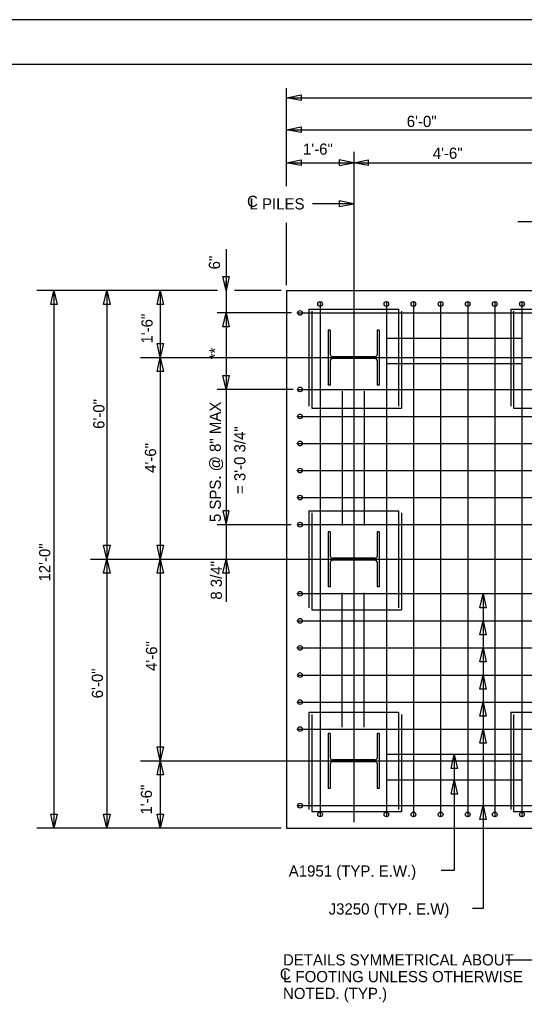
# Model space of a CAD drawing. Extents: x 1970675.2 to 1970711.3, y 796145.2 to 796167.2.
# Drawn here: x 1970688.24 to 1970693.86, y 796156.28 to 796167.25 of the extents above; entities that cross this region are included whole.
import ezdxf

# ---------------------------------------------------------------- set-up
doc = ezdxf.new("R2010")
doc.units = 0
for name, color, linetype in [('BR_AUTO DIMENSION', 7, 'Continuous'), ('BR_BORDER LINES', 7, 'Continuous'), ('BR_CENTER LINES', 7, 'Continuous'), ('BR_CONCRETE', 7, 'Continuous'), ('BR_REBAR', 7, 'Continuous'), ('BR_STRUCTURAL STEEL', 7, 'Continuous'), ('BR_TEXT', 7, 'Continuous'), ('Level 31', 7, 'Continuous')]:
    doc.layers.add(name, color=color, linetype=linetype)

msp = doc.modelspace()

# ---------------------------------------------------------------- linework, layer by layer
at = {"layer": 'BR_AUTO DIMENSION'}
for p, q in [((1970691.212, 796165.389), (1970691.212, 796166.48)), ((1970691.212, 796166.375), (1970697.212, 796166.375)), ((1970691.212, 796166.018), (1970694.212, 796166.018)), ((1970691.212, 796165.65), (1970691.962, 796165.65)), ((1970691.962, 796165.65), (1970694.212, 796165.65)), ((1970691.962, 796165.192), (1970691.501, 796165.192)), ((1970691.212, 796164.284), (1970691.212, 796164.977)), ((1970694.212, 796164.991), (1970693.791, 796164.991)), ((1970690.538, 796164.684), (1970690.538, 796160.748)), ((1970690.538, 796164.224), (1970690.538, 796164.327)), ((1970690.443, 796164.224), (1970688.427, 796164.224)), ((1970688.619, 796164.224), (1970688.619, 796158.224)), ((1970689.208, 796164.224), (1970689.208, 796161.224)), ((1970689.805, 796164.224), (1970689.805, 796163.474)), ((1970691.152, 796164.224), (1970690.631, 796164.224)), ((1970691.268, 796163.974), (1970690.439, 796163.974)), ((1970689.805, 796163.474), (1970689.805, 796161.224)), ((1970691.285, 796163.12), (1970690.439, 796163.12)), ((1970691.265, 796161.61), (1970690.439, 796161.61)), ((1970689.208, 796161.224), (1970689.208, 796158.224)), ((1970689.805, 796161.224), (1970689.805, 796158.224)), ((1970693.404, 796160.839), (1970693.404, 796157.326)), ((1970693.083, 796159.044), (1970693.083, 796157.751)), ((1970689.805, 796158.849), (1970689.805, 796158.75)), ((1970691.152, 796158.224), (1970688.427, 796158.224)), ((1970689.805, 796158.224), (1970689.805, 796158.314)), ((1970693.083, 796157.751), (1970692.938, 796157.751)), ((1970693.404, 796157.326), (1970693.287, 796157.326)), ((1970694.212, 796156.751), (1970693.66, 796156.751))]:
    msp.add_line(p, q, dxfattribs=at)
for points in [[(1970691.374, 796166.344), (1970691.212, 796166.375), (1970691.374, 796166.407)], [(1970691.374, 796165.987), (1970691.212, 796166.018), (1970691.374, 796166.049)], [(1970691.374, 796165.619), (1970691.212, 796165.65), (1970691.374, 796165.681)], [(1970691.799, 796165.619), (1970691.962, 796165.65), (1970691.799, 796165.681)], [(1970692.124, 796165.619), (1970691.962, 796165.65), (1970692.124, 796165.681)], [(1970691.799, 796165.161), (1970691.962, 796165.192), (1970691.799, 796165.223)], [(1970690.574, 796164.38), (1970690.538, 796164.224), (1970690.502, 796164.38)], [(1970688.583, 796164.068), (1970688.619, 796164.224), (1970688.655, 796164.068)], [(1970689.172, 796164.068), (1970689.208, 796164.224), (1970689.244, 796164.068)], [(1970689.769, 796164.068), (1970689.805, 796164.224), (1970689.841, 796164.068)], [(1970690.502, 796163.818), (1970690.538, 796163.974), (1970690.574, 796163.818)], [(1970689.841, 796163.632), (1970689.805, 796163.476), (1970689.769, 796163.632)], [(1970689.769, 796163.318), (1970689.805, 796163.474), (1970689.841, 796163.318)], [(1970690.574, 796163.276), (1970690.538, 796163.12), (1970690.502, 796163.276)], [(1970690.502, 796161.766), (1970690.538, 796161.61), (1970690.574, 796161.766)], [(1970689.244, 796161.38), (1970689.208, 796161.224), (1970689.172, 796161.38)], [(1970689.841, 796161.38), (1970689.805, 796161.224), (1970689.769, 796161.38)], [(1970689.172, 796161.068), (1970689.208, 796161.224), (1970689.244, 796161.068)], [(1970689.769, 796161.068), (1970689.805, 796161.224), (1970689.841, 796161.068)], [(1970690.502, 796161.068), (1970690.538, 796161.224), (1970690.574, 796161.068)], [(1970693.368, 796160.683), (1970693.404, 796160.839), (1970693.44, 796160.683)], [(1970693.368, 796160.381), (1970693.404, 796160.537), (1970693.44, 796160.381)], [(1970693.368, 796160.079), (1970693.404, 796160.235), (1970693.44, 796160.079)], [(1970693.368, 796159.776), (1970693.404, 796159.932), (1970693.44, 796159.776)], [(1970693.368, 796159.474), (1970693.404, 796159.63), (1970693.44, 796159.474)], [(1970693.368, 796159.172), (1970693.404, 796159.328), (1970693.44, 796159.172)], [(1970689.841, 796159.13), (1970689.805, 796158.974), (1970689.769, 796159.13)], [(1970689.769, 796158.818), (1970689.805, 796158.974), (1970689.841, 796158.818)], [(1970693.047, 796158.888), (1970693.083, 796159.044), (1970693.119, 796158.888)], [(1970693.047, 796158.603), (1970693.083, 796158.759), (1970693.119, 796158.603)], [(1970693.368, 796158.318), (1970693.404, 796158.474), (1970693.44, 796158.318)], [(1970688.655, 796158.38), (1970688.619, 796158.224), (1970688.583, 796158.38)], [(1970689.244, 796158.38), (1970689.208, 796158.224), (1970689.172, 796158.38)], [(1970689.841, 796158.38), (1970689.805, 796158.224), (1970689.769, 796158.38)]]:
    msp.add_lwpolyline(points, close=True, dxfattribs=at)
at = {"layer": 'BR_BORDER LINES'}
msp.add_line((1970710.736, 796166.746), (1970677.07, 796166.746), dxfattribs=at)
at = {"layer": 'BR_CENTER LINES'}
for p, q in [((1970691.962, 796165.772), (1970691.962, 796158.288)), ((1970689.584, 796163.474), (1970698.529, 796163.474)), ((1970689.028, 796161.224), (1970699.302, 796161.224)), ((1970689.584, 796158.974), (1970698.439, 796158.974))]:
    msp.add_line(p, q, dxfattribs=at)
at = {"layer": 'BR_CONCRETE'}
for p, q in [((1970691.212, 796164.224), (1970697.212, 796164.224)), ((1970691.212, 796164.224), (1970691.212, 796158.224)), ((1970691.212, 796158.224), (1970697.212, 796158.224))]:
    msp.add_line(p, q, dxfattribs=at)
at = {"layer": 'BR_REBAR'}
for p, q in [((1970691.587, 796164.099), (1970691.587, 796158.349)), ((1970692.326, 796164.099), (1970692.326, 796158.349)), ((1970692.628, 796164.099), (1970692.628, 796158.349)), ((1970692.931, 796164.099), (1970692.931, 796158.349)), ((1970693.233, 796164.099), (1970693.233, 796158.349)), ((1970693.535, 796164.099), (1970693.535, 796158.349)), ((1970693.837, 796164.099), (1970693.837, 796158.349)), ((1970691.337, 796163.974), (1970697.087, 796163.974)), ((1970691.462, 796164.016), (1970692.462, 796164.016)), ((1970691.462, 796164.016), (1970691.462, 796162.932)), ((1970691.494, 796163.993), (1970691.494, 796162.91)), ((1970692.462, 796164.016), (1970692.462, 796162.932)), ((1970692.494, 796163.993), (1970692.494, 796162.91)), ((1970693.712, 796164.016), (1970694.712, 796164.016)), ((1970693.712, 796164.016), (1970693.712, 796162.932)), ((1970693.744, 796163.993), (1970693.744, 796162.91)), ((1970693.837, 796163.689), (1970692.337, 796163.689)), ((1970693.837, 796163.405), (1970692.337, 796163.405)), ((1970691.337, 796163.12), (1970697.087, 796163.12)), ((1970691.833, 796163.099), (1970691.833, 796161.599)), ((1970692.08, 796163.099), (1970692.08, 796161.599)), ((1970691.337, 796162.818), (1970697.087, 796162.818)), ((1970691.494, 796162.91), (1970692.494, 796162.91)), ((1970693.744, 796162.91), (1970694.744, 796162.91)), ((1970691.337, 796162.516), (1970697.087, 796162.516)), ((1970691.337, 796162.214), (1970697.087, 796162.214)), ((1970691.337, 796161.912), (1970697.087, 796161.912)), ((1970691.462, 796161.766), (1970692.462, 796161.766)), ((1970691.462, 796161.766), (1970691.462, 796160.682)), ((1970691.494, 796161.743), (1970691.494, 796160.66)), ((1970692.462, 796161.766), (1970692.462, 796160.682)), ((1970692.494, 796161.743), (1970692.494, 796160.66)), ((1970697.087, 796161.61), (1970691.337, 796161.61)), ((1970692.42, 796161.224), (1970696.003, 796161.224)), ((1970697.087, 796160.839), (1970691.337, 796160.839)), ((1970691.833, 796159.349), (1970691.833, 796160.849)), ((1970692.08, 796159.349), (1970692.08, 796160.849)), ((1970691.494, 796160.66), (1970692.494, 796160.66)), ((1970691.337, 796160.537), (1970697.087, 796160.537)), ((1970691.337, 796160.235), (1970697.087, 796160.235)), ((1970691.337, 796159.932), (1970697.087, 796159.932)), ((1970691.337, 796159.63), (1970697.087, 796159.63)), ((1970691.462, 796159.516), (1970692.462, 796159.516)), ((1970691.462, 796159.516), (1970691.462, 796158.432)), ((1970691.494, 796159.493), (1970691.494, 796158.41)), ((1970692.462, 796159.516), (1970692.462, 796158.432)), ((1970692.494, 796159.493), (1970692.494, 796158.41)), ((1970693.712, 796159.516), (1970694.712, 796159.516)), ((1970693.712, 796159.516), (1970693.712, 796158.432)), ((1970693.744, 796159.493), (1970693.744, 796158.41)), ((1970691.337, 796159.328), (1970697.087, 796159.328)), ((1970693.837, 796159.044), (1970692.337, 796159.044)), ((1970693.837, 796158.759), (1970692.337, 796158.759)), ((1970691.337, 796158.474), (1970697.087, 796158.474)), ((1970691.494, 796158.41), (1970692.494, 796158.41)), ((1970693.744, 796158.41), (1970694.744, 796158.41))]:
    msp.add_line(p, q, dxfattribs=at)
for centre in [(1970691.587, 796164.073), (1970692.326, 796164.073), (1970692.628, 796164.073), (1970692.931, 796164.073), (1970693.233, 796164.073), (1970693.535, 796164.073), (1970693.837, 796164.073), (1970691.363, 796163.974), (1970691.363, 796163.12), (1970691.363, 796162.818), (1970691.363, 796162.516), (1970691.363, 796162.214), (1970691.363, 796161.912), (1970691.363, 796161.61), (1970691.363, 796160.839), (1970691.363, 796160.537), (1970691.363, 796160.235), (1970691.363, 796159.932), (1970691.363, 796159.63), (1970691.363, 796159.328), (1970691.363, 796158.474), (1970691.587, 796158.376), (1970692.326, 796158.376), (1970692.628, 796158.376), (1970692.931, 796158.376), (1970693.233, 796158.376), (1970693.535, 796158.376), (1970693.837, 796158.376)]:
    msp.add_circle(centre, 0.0265, dxfattribs=at)
at = {"layer": 'BR_STRUCTURAL STEEL'}
for p, q in [((1970691.678, 796163.781), (1970691.678, 796163.167)), ((1970691.699, 796163.781), (1970691.678, 796163.781)), ((1970691.699, 796163.781), (1970691.699, 796163.513)), ((1970692.225, 796163.781), (1970692.225, 796163.513)), ((1970692.246, 796163.781), (1970692.225, 796163.781)), ((1970692.246, 796163.781), (1970692.246, 796163.167)), ((1970692.197, 796163.485), (1970691.727, 796163.485)), ((1970691.699, 796163.436), (1970691.699, 796163.167)), ((1970692.197, 796163.464), (1970691.727, 796163.464)), ((1970692.225, 796163.436), (1970692.225, 796163.167)), ((1970691.699, 796163.167), (1970691.678, 796163.167)), ((1970692.246, 796163.167), (1970692.225, 796163.167)), ((1970691.678, 796161.531), (1970691.678, 796160.917)), ((1970691.699, 796161.531), (1970691.678, 796161.531)), ((1970691.699, 796161.531), (1970691.699, 796161.263)), ((1970692.225, 796161.531), (1970692.225, 796161.263)), ((1970692.246, 796161.531), (1970692.225, 796161.531)), ((1970692.246, 796161.531), (1970692.246, 796160.917)), ((1970691.699, 796161.186), (1970691.699, 796160.917)), ((1970692.197, 796161.235), (1970691.727, 796161.235)), ((1970692.197, 796161.214), (1970691.727, 796161.214)), ((1970692.225, 796161.186), (1970692.225, 796160.917)), ((1970691.699, 796160.917), (1970691.678, 796160.917)), ((1970692.246, 796160.917), (1970692.225, 796160.917)), ((1970691.678, 796159.281), (1970691.678, 796158.667)), ((1970691.699, 796159.281), (1970691.678, 796159.281)), ((1970691.699, 796159.281), (1970691.699, 796159.013)), ((1970692.225, 796159.281), (1970692.225, 796159.013)), ((1970692.246, 796159.281), (1970692.225, 796159.281)), ((1970692.246, 796159.281), (1970692.246, 796158.667)), ((1970692.197, 796158.985), (1970691.727, 796158.985)), ((1970691.699, 796158.936), (1970691.699, 796158.667)), ((1970692.197, 796158.964), (1970691.727, 796158.964)), ((1970692.225, 796158.936), (1970692.225, 796158.667)), ((1970691.699, 796158.667), (1970691.678, 796158.667)), ((1970692.246, 796158.667), (1970692.225, 796158.667))]:
    msp.add_line(p, q, dxfattribs=at)
for centre, start, end in [((1970691.727, 796163.513), 180, 270), ((1970692.197, 796163.513), 270, 360), ((1970691.727, 796163.436), 90, 180), ((1970692.197, 796163.436), 360, 90), ((1970691.727, 796161.263), 180, 270), ((1970691.727, 796161.186), 90, 180), ((1970692.197, 796161.263), 270, 360), ((1970692.197, 796161.186), 360, 90), ((1970691.727, 796159.013), 180, 270), ((1970692.197, 796159.013), 270, 360), ((1970691.727, 796158.936), 90, 180), ((1970692.197, 796158.936), 360, 90)]:
    msp.add_arc(centre, 0.0281, start, end, dxfattribs=at)
at = {"layer": 'Level 31'}
msp.add_line((1970711.236, 796167.246), (1970675.236, 796167.246), dxfattribs=at)

# ---------------------------------------------------------------- texts
at = {"layer": 'BR_AUTO DIMENSION'}
for s, p in [('6\'-0"', (1970692.553, 796166.048)), ('C', (1970690.772, 796165.156)), ('C', (1970691.139, 796156.533))]:
    msp.add_text(s, height=0.125, dxfattribs=at).set_placement(p)
at = {"layer": 'BR_TEXT'}
for s, p in [('1\'-6"', (1970691.396, 796165.739)), ('4\'-6"', (1970692.843, 796165.693)), ('L PILES', (1970690.8, 796165.128)), ('A1951 (TYP. E.W.)', (1970691.237, 796157.682)), ('J3250 (TYP. E.W)', (1970691.682, 796157.259)), ('DETAILS SYMMETRICAL ABOUT ', (1970691.173, 796156.691)), ('L FOOTING UNLESS OTHERWISE', (1970691.173, 796156.504)), ('NOTED. (TYP.)', (1970691.173, 796156.316))]:
    msp.add_text(s, height=0.125, dxfattribs=at).set_placement(p)
for s, p in [('6"', (1970690.471, 796164.459)), ('1\'-6"', (1970689.719, 796163.631)), ('**', (1970690.478, 796163.455)), ('6\'-0"', (1970689.182, 796162.679)), ('5 SPS. @ 8" MAX', (1970690.48, 796161.639)), ('= 3\'-0 3/4"', (1970690.754, 796161.952)), ('4\'-6"', (1970689.758, 796162.188)), ('12\'-0"', (1970688.578, 796160.975)), ('8 3/4"', (1970690.492, 796160.773)), ('4\'-6"', (1970689.769, 796159.977)), ('6\'-0"', (1970689.165, 796159.672)), ('1\'-6"', (1970689.712, 796158.375))]:
    msp.add_text(s, height=0.125, rotation=90, dxfattribs=at).set_placement(p)

doc.saveas('drawing.dxf')
